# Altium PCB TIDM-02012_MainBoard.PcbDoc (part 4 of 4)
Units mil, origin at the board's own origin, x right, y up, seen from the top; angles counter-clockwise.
Board outline 6550 x 5100 mil, 4 copper layers (Top Layer, Layer 1, Layer 2, Bottom Layer), stack 81.2 mil thick; 300 components, 157 nets, 916 pads, 350 vias.
Unrouted connection lines stored in the file: 93.
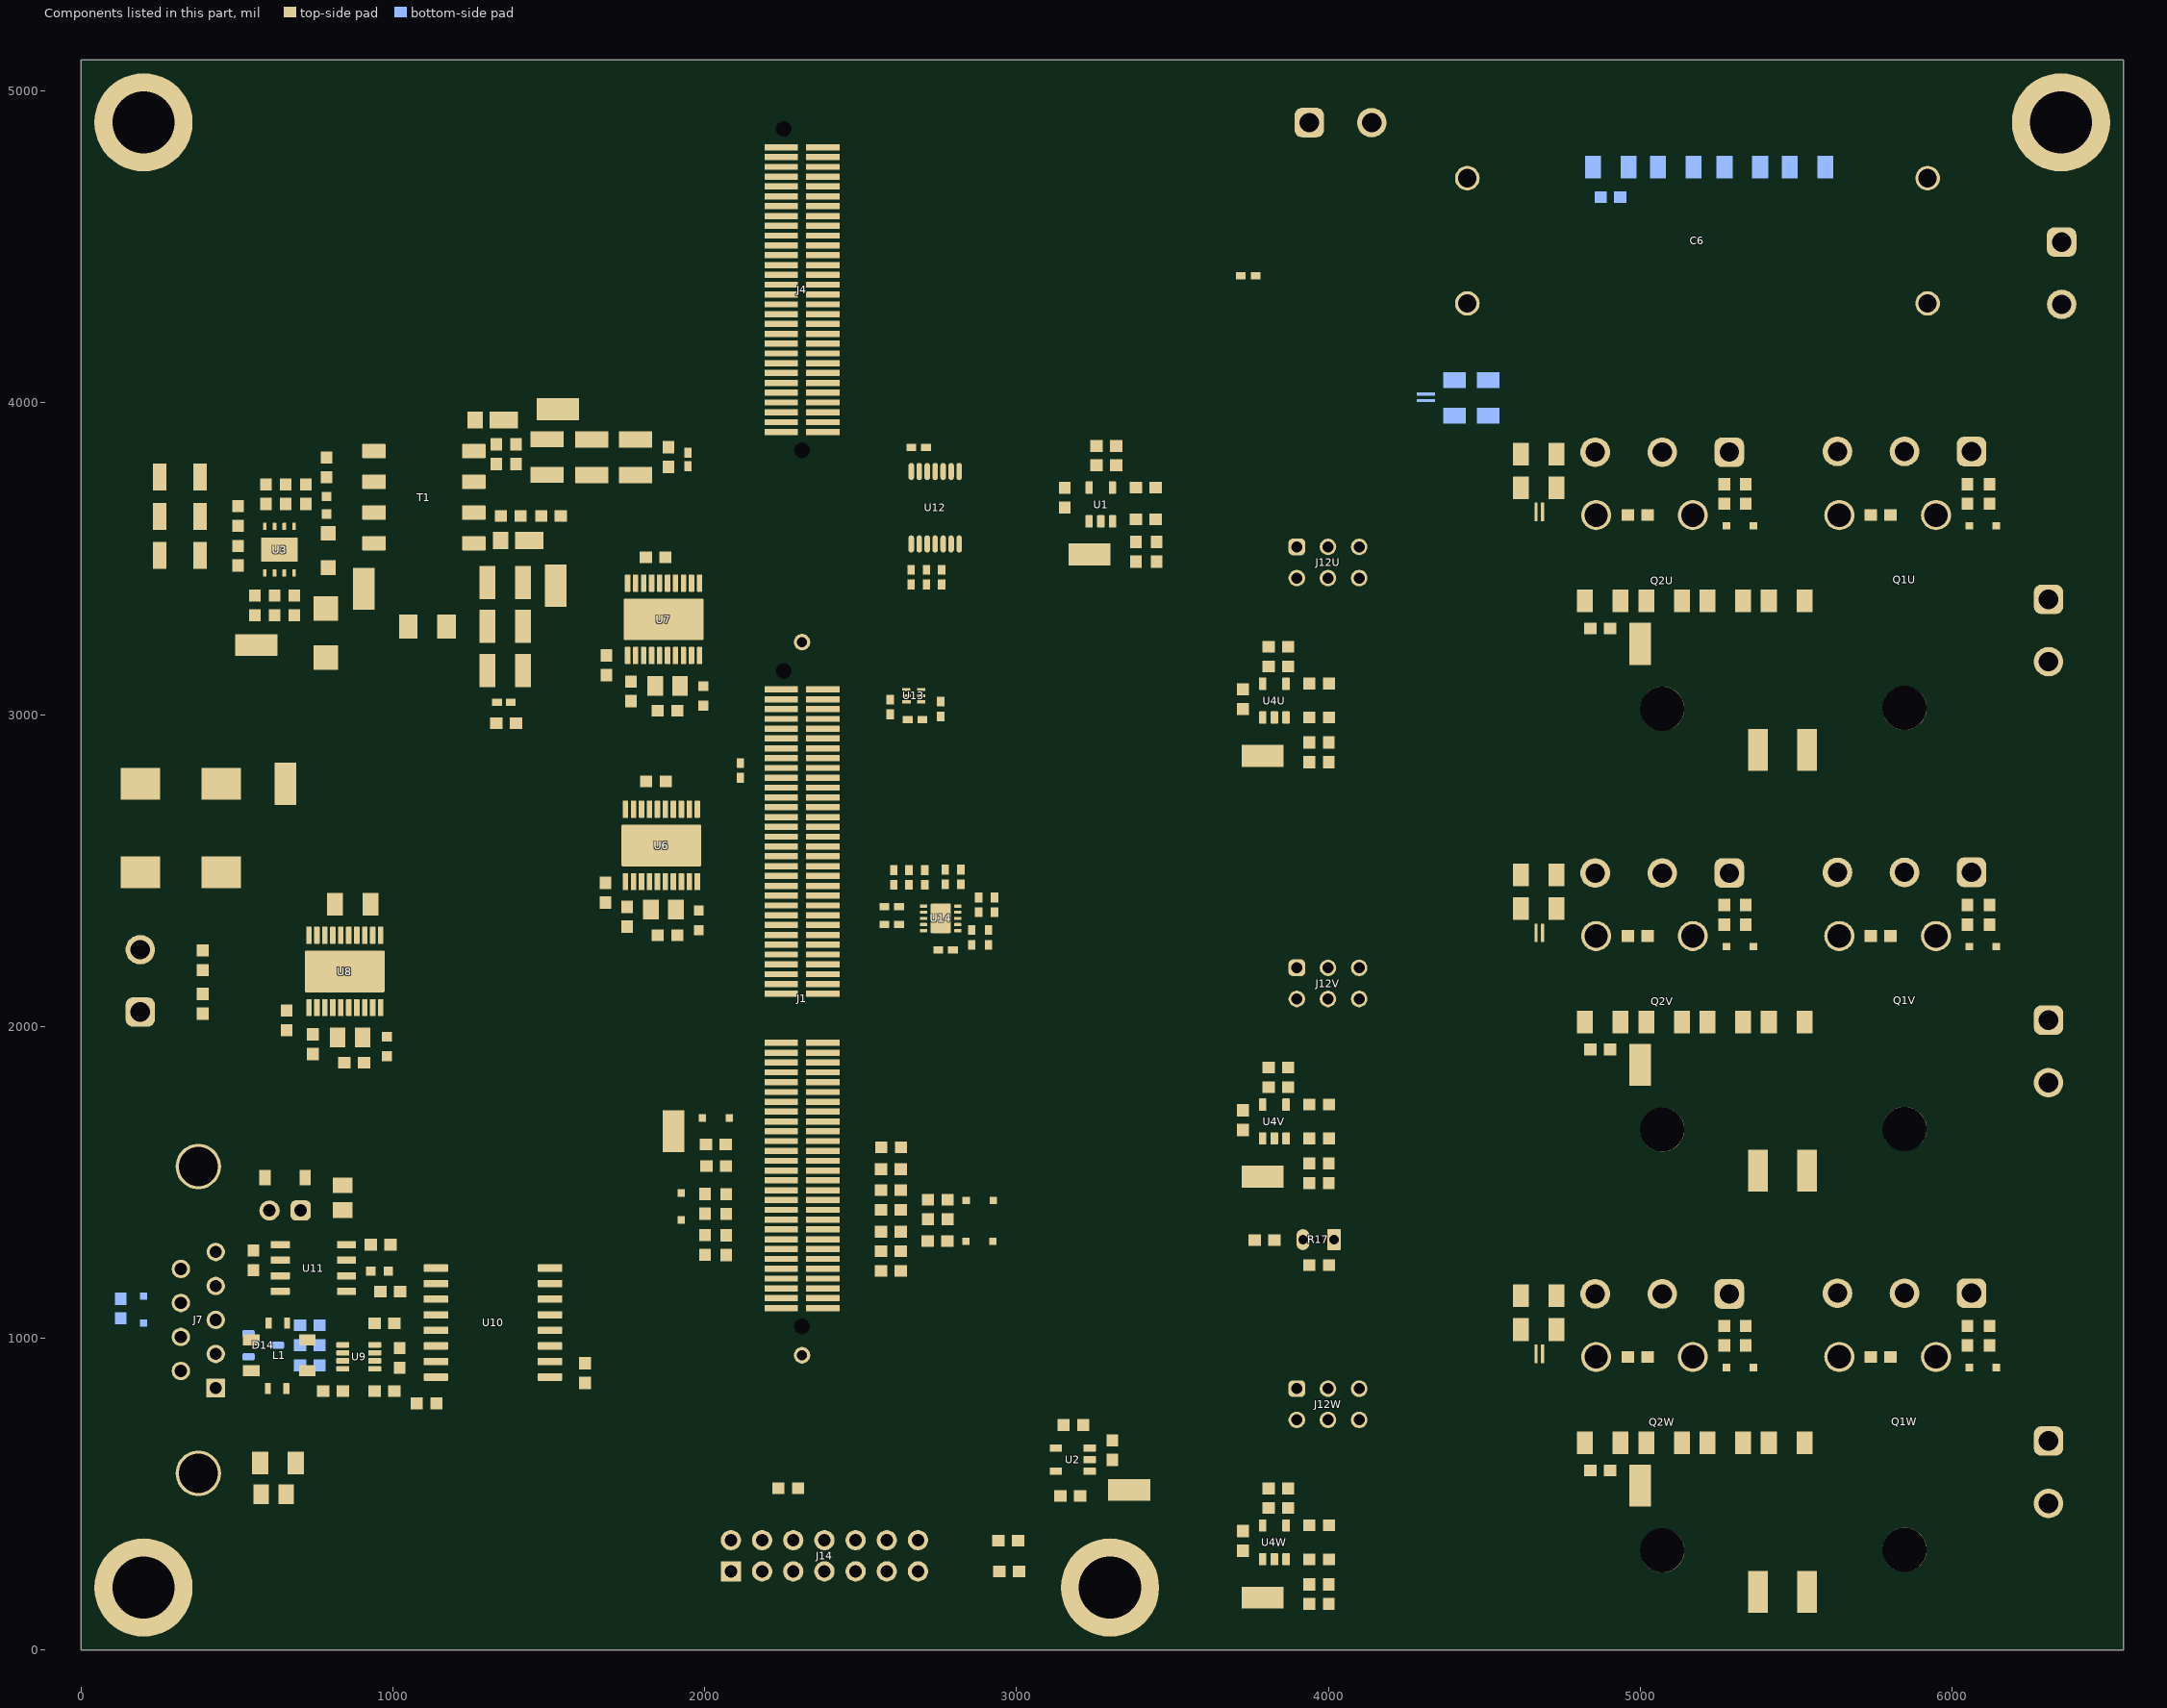
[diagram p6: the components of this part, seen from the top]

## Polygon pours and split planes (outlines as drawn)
GND_MCU on Bottom Layer "BOTTOM_LAYER_GND_MCU_P051" (solid, pour order 51): 1219.43,3944.93 1219.43,2692.41 1462,2449.84 1462,318 1716,64 4023.1,64 4135.65,176.54 4135.65,3784.05 3737.58,4182.11 3737.58,4833.67 3629.91,4941.34 1984.07,4941.34 1219.23,4176.5
S_1W on Bottom Layer "BOTTOM_LAYER_S_1W_P033" (solid, pour order 33): 6404.71,1225.32 6459,1171.02 6459,316 6356,213 5020.07,213 4903.64,329.43 4904.39,330.17 4904.39,1121.94 5007.76,1225.32
S_1V on Bottom Layer "BOTTOM_LAYER_S_1V_P032" (solid, pour order 32): 6404.71,2575.32 6459,2521.02 6459,1666 6356,1563 5020.07,1563 4903.64,1679.43 4904.39,1680.17 4904.39,2471.94 5007.76,2575.32
DC-U on Bottom Layer "BOTTOM_LAYER_DC-U_P042" (solid, pour order 42): 4369.49,3984 4357.23,3971.74 4357.23,3930.59 4244,3817.36 4244,952.54 4359.53,837.01 4746.54,837.01 4809.46,899.92 4809.46,3677.4 4554.64,3932.22 4554.64,3977.81 4548.45,3984
PGND on Bottom Layer "BOTTOM_LAYER_PGND_P039" (solid, pour order 39): 4236.75,4239.42 3928.13,4239.42 3778,4389.56 3778,4978 4745,4981 4828,4898 4828,4377.24 4559.28,4108.52 4559.28,4057.28 4550,4048 4368.02,4048 4357.36,4058.65 4357.27,4118.9
VBUS on Bottom Layer "BOTTOM_LAYER_VBUS_P037" (solid, pour order 37): 5610.66,4988 5869.81,4988 6202.39,4655.42 6202.39,4655.37 6499.16,4655.37 6499.16,4040 5612.19,4040
S_1U on Bottom Layer "BOTTOM_LAYER_S_1U_P031" (solid, pour order 31): 6404.71,3925.32 6459,3871.02 6459,3016 6356,2913 5020.07,2913 4903.64,3029.43 4904.39,3030.17 4904.39,3821.94 5007.76,3925.32
DC-U on Top Layer "Top Layer-DC-U" (solid, pour order 38): 4741.7,36 4244,533.7 4244,3888.02 4312.92,3956.94 4580.28,3956.94 4593.37,3943.85 4593.37,3913.2 4603.57,3903 4628,3903 4642.1,3888.9 4642.1,3674.1 4626,3658 4603.57,3658 4593.37,3647.8 4593.37,3210.3 4779.29,3024.39 5340.31,3024.39 5408.71,2955.98 5408.71,2786.08 5333.63,2711 4705.87,2711 4593.37,2598.5 4593.37,2563.2 4603.57,2553 4628,2553 4642.1,2538.9 4642.1,2324.1 4626,2308 4603.57,2308 4593.37,2297.8 4593.37,1860.3 4779.29,1674.39 5340.31,1674.39 5408.71,1605.98 5408.71,1436.08 5333.63,1361 4694.89,1361 4593.37,1259.48 4593.37,1213.2 4603.57,1203 4628,1203 4642.1,1188.9 4642.1,974.1 4626,958 4603.57,958 4593.37,947.8 4593.37,580.88 4849.87,324.39 5340.31,324.39 5408.71,255.98 5408.71,115.71 5329,36 4894,36
VCC33 on Top Layer "TOP_LAYER_VCC33_P048" (solid, pour order 48): 1801.97,2367.84 1773.56,2339.43 1773.56,2175.29 1793.23,2155.62 1865.41,2155.62 1881.16,2171.36 1880.84,2171.68 1880.84,2328.21 1841.21,2367.84
NetC32_2 on Top Layer "TOP_LAYER_NETC32_2_P045" (solid, pour order 45): 849.5,3492.43 836.93,3505 741.01,3505 666.55,3579.46 666.55,3673.8 692.1,3699.36 953,3699.36 977,3675.36 977,3524 977,3492.49 938.84,3454.33 875.02,3454.33 849.5,3479.85
VCC5_LV on Top Layer "TOP_LAYER_VCC5_LV_P044" (solid, pour order 44): 794.45,1935.72 776.46,1917.74 776.46,1859.68 793.14,1843 811,1843 863.92,1843 875.59,1854.67 875.59,1918.56 858.42,1935.72 858.42,1993.17 815.56,2036.04 807.93,2036.04 794.45,2035.97
PGND on Top Layer "TOP_LAYER_PGND_P040" (solid, pour order 40): 4236.75,4239.42 3928.13,4239.42 3778,4389.56 3778,4978 4745,4981 4828,4898 4828,4377.24 4559.28,4108.52 4559.28,4057.28 4550,4048 4368.02,4048 4357.36,4058.65 4357.27,4118.9
VBUS on Top Layer "TOP_LAYER_VBUS_P036" (solid, pour order 36): 5683.71,4988 5869.81,4988 6202.39,4655.42 6202.39,4655.37 6499.16,4655.37 6499.16,4040 5685.24,4040
VCC33 on Layer 2 "LAYER_2_VCC33_P055" (solid, pour order 55): 1219.43,3944.93 1219.43,2692.41 1462,2449.84 1462,318 1716,64 4023.1,64 4135.65,176.54 4135.65,3784.05 3737.58,4182.11 3737.58,4833.67 3629.91,4941.34 1984.07,4941.34 1219.23,4176.5
VCC5_LV on Layer 2 "LAYER_2_VCC5_LV_P047" (solid, pour order 47): 364.15,334.2 367.64,337.7 958.7,337.7 1183,562 1183,1998 1090.94,2090.06 610.06,2090.06 97,1577 97,601.35
VBUS on Layer 2 "LAYER_2_VBUS_P035" (solid, pour order 35): 5475,4988 5869.81,4988 6202.44,4655.37 6499.16,4655.37 6499.16,325.16 6252.27,78.27 5515.45,78.27 5420.5,173.22 5420.5,4933.5
GND_MCU on Layer 1 "LAYER_1_GND_MCU_P054" (solid, pour order 54): 1219.43,3944.93 1219.43,2692.41 1462,2449.84 1462,318 1716,64 4023.1,64 4135.65,176.54 4135.65,3784.05 3737.58,4182.11 3737.58,4833.67 3629.91,4941.34 1984.07,4941.34 1219.23,4176.5
GND on Layer 1 "LAYER_1_GND_P046" (solid, pour order 46): 373.57,324.77 97,601.35 97,4025 360,4288 749,4288 972,4065 972,2556 1183,2345 1183,562 949.16,328.16
DC-U on Layer 1 "LAYER_1_DC-U_P043" (solid, pour order 43): 4321.83,3936.34 4244,3858.51 4244,952.54 4359.53,837.01 4756.01,837.01 4931.47,1012.47 4931.47,3810.88 4806.01,3936.34
PGND on Layer 1 "LAYER_1_PGND_P041" (solid, pour order 41): 4236.75,4239.42 3928.13,4239.42 3778,4389.56 3778,4978 4745,4981 4828,4898 4828,4377.24 4559.28,4108.52 4559.28,4057.28 4550,4048 4368.02,4048 4357.36,4058.65 4357.27,4118.9
VBUS on Layer 1 "LAYER_1_VBUS_P034" (solid, pour order 34): 5475,4988 5869.81,4988 6202.44,4655.37 6499.16,4655.37 6499.16,325.16 6252.27,78.27 5515.45,78.27 5420.5,173.22 5420.5,4933.5

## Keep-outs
Keep-Out Layer:
  text ".Layer_Name" at 577,-858.49 h60

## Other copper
Top Layer:
  region net VBUS: 5504.36,277.07 5633,277.07 5633,97 5632,98 5504.79,98
  region net S_2W: 4701,1207 4701,994 4708,987 4809.46,987 4905,1082.54 4905,1179.47 4877.47,1207
  region net VBUS: 5504.36,1627.07 5633,1627.07 5633,1447 5632,1448 5504.79,1448
  region net S_2V: 4701,2557 4701,2344 4708,2337 4809.46,2337 4905,2432.54 4905,2529.47 4877.47,2557
  region net VBUS: 5504.36,2977.07 5633,2977.07 5633,2797 5632,2798 5504.79,2798
  region net S_2U: 4701,3907 4701,3694 4708,3687 4809.46,3687 4905,3782.54 4905,3879.47 4877.47,3907
  text ".Layer_Name" at 577,-858.49 h60
Bottom Layer:
  text ".Layer_Name" at 577,-858.49 h60

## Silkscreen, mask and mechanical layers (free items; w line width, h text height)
Top Overlay:
  lines w10: 935.68,62.68 1540.68,62.68 1540.68,551.86 935.68,551.86 935.68,62.68 ; 3849.03,688.37 4149.03,688.37 4149.03,887.58 3849.03,887.58 3849.03,688.37 ; 3849.03,2038.37 4149.03,2038.37 4149.03,2237.58 3849.03,2237.58 3849.03,2038.37 ; 3849.03,3388.37 4149.03,3388.37 4149.03,3587.58 3849.03,3587.58 3849.03,3388.37
  text "HVDC-" at 3905,4634 h60
  text "'.PRJ_Number'.PCB_Rev" at 596,4263 h108.27
  text "High Voltage Danger" at 2646,4144 h60
  text "HVDC+" at 6145.37,4060 h60
  text "800V" at 6137.71,3961.58 h100
  text "MAX" at 6342.71,3959.52 h60
  text "U" at 6378.84,3554.02 h60
  text "9 NM Torque" at 5460.26,3191.72 h60
  text "+" at 382.77,2313.99 h60
  text "V" at 6362.02,2208.41 h60
  text "-" at 382.77,1930.91 h60
  text "VBAT" at 162.08,1796.7 h60
  text "12V" at 190,1698.01 h100
  text "W" at 6362.02,845.46 h60
  text "CAN_H: 7 / CAN_L: 2 / LIN: 8 / GND: 3, 5" at 972,76.05 h60
  text "JTAG" at 2288,44.52 h60
  text ".Layer_Name" at 577,-858.49 h60
Bottom Overlay:
  text ".Layer_Name" at 577,-858.49 h60
Top Paste:
  text ".Layer_Name" at 577,-858.49 h60
Bottom Paste:
  text ".Layer_Name" at 577,-858.49 h60
Top Solder:
  text ".Layer_Name" at 577,-858.49 h60
  text ".Layer_Name" at 577,-858.49 h60
Bottom Solder:
  text ".Layer_Name" at 577,-858.49 h60
Drill Guide:
  text ".Layer_Name" at 577,-858.49 h60
M1 Board Outline:
  the board outline again, w10
  text ".Layer_Name" at 577,-858.49 h60
M2 Board Dimensions:
  rectangle: 0,-275 125,-150
  rectangle: 125,-400 500,-275
  lines w7: 0,-275 1000,-275 ; 125,-400 125,-150 ; 250,-400 250,-150 ; 500,-400 500,-150 ; 750,-400 750,-150 ; 0,-400 1000,-400 1000,-150 0,-150 0,-400
  text ".Layer_Name" at 577,-858.49 h60
M3 3D STEP Top:
  text ".Layer_Name" at 577,-858.49 h60
M4 3D STEP Bottom:
  text ".Layer_Name" at 577,-858.49 h60
M5 Assembly Top:
  lines w10: -292,-930.17 6308,-930.17 ; -292,-726.83 6310,-726.83 ; -292,-523.5 -292,-1133.5 3713,-1133.5 6310,-1133.5 6310,-523.5 -291.5,-523.5 -291.5,-1133.5 1284,-1133.5 ; 2173,-1133.5 2173,-523.5 ; 3440,-726.83 3440,-523.5 ; 4280,-726.83 4280,-523.5 ; 4902,-1140 4902,-937.17
  text "COMPONENTS MARKED 'DNP' SHOULD NOT BE POPULATED." at 1153.5,-318.5 h60
  text "ASSEMBLY VARIANT:" at 1153,-434 h60
  text ".VariantName" at 2189,-434 h60
  text "PCB VIEWED FROM TOP SIDE" at -228.5,-655.67 h60
  text "BOARD #:" at 2248,-655.67 h60
  text ".PRJ_Number" at 2793.5,-655.67 h60
  text "REV:" at 3638,-655.67 h60
  text ".PCB_Rev" at 3929.5,-655.67 h60
  text "SVN REV:" at 4476,-655.67 h60
  text ".VersionControl_RevNumber" at 4982,-655.67 h60
  text "TID #:" at 2248,-859 h60
  text ".TID" at 2793.5,-859 h60
  text "PLOT NAME =" at -228.5,-1064.34 h60
  text ".plot_File_Name" at 577,-1064.34 h60
  text "GENERATED    :" at 2250,-1064.34 h60
  text ".Print_Date" at 3119.5,-1064.34 h60
  text ".Print_Time" at 3848.5,-1064.34 h60
  text "TEXAS INSTRUMENTS" at 5113,-1064.34 h60
M6 Assembly Bottom:
  lines w10: -292.5,-727.33 6309.5,-727.33 ; -290.5,-930.67 6309.5,-930.67 ; 1115.5,-1140.5 1115.5,-937.67 ; 1737.5,-727.33 1737.5,-524 ; 2577.5,-727.33 2577.5,-524 ; 3844.5,-1134 3844.5,-524 ; 4733.5,-1134 6309,-1134 6309,-524 -292.5,-524 -292.5,-1134 2304.5,-1134 6309.5,-1134 6309.5,-524
  text "COMPONENTS MARKED 'DNP' SHOULD NOT BE POPULATED." at 6102,-318 h60
  text ".VariantName" at 5058,-434 h60
  text "ASSEMBLY VARIANT:" at 6097,-434 h60
  text ".VersionControl_RevNumber" at 1035.5,-656.17 h60
  text "SVN REV:" at 1541.5,-656.17 h60
  text ".PCB_Rev" at 2088,-656.17 h60
  text "REV:" at 2379.5,-656.17 h60
  text ".PRJ_Number" at 3224,-656.17 h60
  text "BOARD #:" at 3769.5,-656.17 h60
  text "PCB VIEWED FROM BOTTOM SIDE" at 6246,-656.17 h60
  text ".TID" at 3224,-859.5 h60
  text "TID #:" at 3769.5,-859.5 h60
  text "TEXAS INSTRUMENTS" at 904.5,-1064.84 h60
  text ".Print_Time" at 2169,-1064.84 h60
  text ".Print_Date" at 2898,-1064.84 h60
  text "GENERATED    :" at 3767.5,-1064.84 h60
  text ".plot_File_Name" at 5440.5,-1064.84 h60
  text "PLOT NAME =" at 6246,-1064.84 h60
M9 Title Sheet:
  drawing of 57 lines, arcs and shapes, not listed
  text "1" at 739.84,8036.5 h70
  text "2" at 3235.5,8036.5 h70
  text "3" at 5724.84,8036.5 h70
  text "4" at 8231.51,8036.5 h70
  text "5" at 10730.5,8036.5 h70
  text "6" at 13235.5,8036.5 h70
  text "A" at -416.5,6893.5 h70
  text "A" at 14383.5,6893.5 h70
  text "B" at -416.5,4513.5 h70
  text "B" at 14383.5,4513.5 h70
  text "C" at -416.5,2138.5 h70
  text "C" at 14383.5,2138.5 h70
  text "PROJECT TITLE:" at 11343.5,277.5 h45
  text ".PRJ_Title" at 11393.5,144.17 h70
  text "DESIGNED FOR:" at 11343.5,-23.5 h45
  text ".PRJ_Customer" at 11393.5,-163.5 h70
  text "D" at -416.5,-231.5 h70
  text "D" at 14383.5,-231.5 h70
  text "FILE NAME:" at 11343.5,-323.5 h45
  text ".PCB_File_Name_No_Path" at 11393.5,-443.5 h70
  text "Texas Instruments (TI) and/or its licensors do not warrant the accuracy or completeness of this specification" at 6374,-605.34 h45
  text "ENGINEER:" at 11343.5,-613.5 h45
  text "LAYOUT BY:" at 12848.5,-613.5 h45
  text "or any information contained therein. TI and/or its licensors do not warrant that this design will meet" at 6329.01,-718 h45
  text ".PRJ_Engineer" at 11393.5,-768.49 h70
  text ".PCB_Layout" at 12899,-768.49 h70
  text "the specifications, will be suitable for your application or fit for any particular purpose, or will operate in" at 6329.01,-830.67 h45
  text ".Layer_Name" at 577,-858.49 h60
  text "ALTIUM DESIGNER VERSION:" at 12848.5,-923.5 h45
  text "an implementation. TI and/or its licensors do not warrant that the design is production worthy. You should" at 6329.01,-943.33 h45
  text "completely validate and test your design implementation to confirm the system functionality for your application." at 6374,-1056 h45
  text ".print_Scale" at 11393.5,-1056.83 h70
  text ".Application_BuildNumber" at 12899,-1056.83 h70
  text "1" at 739.84,-1263.5 h70
  text "2" at 3235.5,-1263.5 h70
  text "3" at 5724.84,-1263.5 h70
  text "4" at 8231.51,-1263.5 h70
  text "5" at 10730.5,-1263.5 h70
  text "6" at 13235.5,-1263.5 h70
M10 Fab Notes:
  drawing of 189 lines, arcs and shapes, not listed
  text "DESIGN INFORMATION" at 12382.02,6356.17 h60
  text "MIN. TRACK WIDTH:" at 11737.46,6224.05 h60
  text "8" at 12833.7,6224.05 h60
  text "MIL" at 12988.46,6224.05 h60
  text "7.874" at 12667.32,6102.36 h60
  text "MIN. CLEARANCE:" at 11737.46,6099.92 h60
  text "MIL" at 12988.46,6099.92 h60
  text "MIN. VIA PAD SIZE:" at 11737.46,5975.8 h60
  text "24" at 12803.71,5975.8 h60
  text "MIL" at 12988.46,5975.8 h60
  text "0.05mm (2MIL)" at 12432.46,5845.9 h60
  text "MINIMUM ANNULAR RING" at 11408.23,5837.67 h60
  text "EXTERNAL" at 13140.46,5837.67 h60
  text "PER" at 11608.23,5727.55 h60
  text "IPC-D-275 CLASS 2 LEVEL C" at 11828.23,5727.54 h60
  text "MIL, HOLES" at 13316.46,5627.07 h60
  text "+/-" at 12924,5618.48 h60
  text "+/-" at 13778,5618.48 h60
  text "REGISTRATION TOLERANCES:" at 11408.23,5617.42 h60
  text "METAL" at 12608,5617.42 h60
  text "5" at 13184.2,5617.42 h60
  text "3" at 14017.2,5617.42 h60
  text "MIL" at 14133.46,5617.42 h60
  text "HOLE SIZE TOLERANCE (UNLESS OTHERWISE SPECIFIED):" at 11408.23,5519.1 h60
  text "+/-" at 13778,5516.23 h60
  text "3" at 14017.2,5515.17 h60
  text "MIL" at 14133.46,5515.17 h60
  text "MATERIAL:" at 11333.46,5377.52 h60
  text "FR-4 High Tg" at 12319.9,5249 h60
  text "X" at 12175.46,5241.01 h60
  text "FR-408" at 11754.46,5236.49 h60
  text "OTHER" at 13242.46,5236.49 h60
  text "62 MIL (1.6mm) +/-10%" at 12074.56,5093.46 h60
  text "X" at 11954.46,5091.01 h60
  text "THICKNESS:" at 11408.23,5085.24 h60
  text "OTHER" at 13359.46,5085.24 h60
  text "TOLERANCE:" at 11408.23,4946.92 h60
  text "X" at 12256.46,4946.92 h60
  text "ANSI IPC-6012 TYPE 3 CLASS 2" at 12434.48,4946.92 h60
  text "OTHER +/-" at 12434.46,4802.73 h60
  text "BOW & TWIST:" at 11408.23,4657.54 h60
  text "X" at 12256.46,4657.54 h60
  text "ANSI IPC-6012 TYPE 3 CLASS 2" at 12434.48,4657.54 h60
  text "OTHER +/-" at 12434.46,4510.85 h60
  text "DRILLING:" at 11333.46,4380.23 h60
  text "NC_DRILL FILES" at 13094.46,4275.04 h60
  text "REFERENCE:" at 11408.23,4271.1 h60
  text "X" at 12065.46,4271.01 h60
  text "AS SHOWN" at 12243.46,4271.1 h60
  text "X" at 12966.46,4271.1 h60
  text "OTHER" at 13392.46,4128.85 h60
  text "PTH COPPER THICKNESS:" at 11407.91,4125.32 h60
  text "X" at 12547.14,4125.32 h60
  text "20-30 um" at 12675.14,4125.32 h60
  text "BOARD FINISH:" at 11333.46,3977.73 h60
  text "SILKSCREEN:" at 11488.68,3867.6 h60
  text "X" at 12446.46,3867.6 h60
  text "TOP" at 12563.46,3867.6 h60
  text "X" at 12956.46,3867.6 h60
  text "BOTTOM" at 13074.46,3867.6 h60
  text "SILKSCREEN COLOR:" at 11488.68,3712.41 h60
  text "X" at 12445.46,3712.41 h60
  text "WHITE" at 12563.46,3712.41 h60
  text "OTHER" at 13074.46,3712.41 h60
  text "X" at 12576.46,3568.96 h60
  text "GREEN" at 12694.46,3568.96 h60
  text "OTHER" at 13312.46,3568.96 h60
  text "SOLDER RESIST COLOR:" at 11488.68,3562.1 h60
  text "X" at 12576.46,3414.71 h60
  text "MATTE" at 12694.46,3414.71 h60
  text "SEMI-GLOSS" at 13312,3414.07 h60
  text "IMMERSION GOLD (ENIG)" at 12394.46,3241.94 h60
  text "ENEPIG" at 13732,3234.72 h60
  text "SURFACE FINISH:" at 11333.46,3233.72 h60
  text "X" at 12216.46,3233.72 h60
  text "IMM. TIN/SILVER OR EQUIV" at 11663,3096.4 h60
  text "OTHER" at 13094.46,3092.47 h60
  text "ARRAY/PANEL:" at 11333.46,2937.09 h60
  text "CUT AND TRIM PER M1 BOARD OUTLINE" at 12394.46,2928.87 h60
  text "N.C. ROUTE" at 12394.46,2792.9 h60
  text "X" at 13082.46,2792.9 h60
  text "V. SCORE" at 13260.46,2792.9 h60
  text "CERTIFICATION:" at 11333.46,2663.77 h60
  text "MATERIALS AND WORKMANSHIP FOR ALL PCBS" at 12058.46,2663.77 h60
  text "TO MEET OR EXCEED THE REQUIREMENTS OF:" at 12058.46,2569.71 h60
  text "X" at 11695.97,2441.08 h60
  text "ANSI IPC-A-600F CLASS ->" at 11823.96,2441.08 h60
  text "X" at 13471.97,2441.08 h60
  text "2" at 13581.96,2441.08 h60
  text "1" at 13266.96,2439.58 h60
  text "3" at 13935.96,2439.58 h60
  text "X" at 12507.97,2293.39 h60
  text "RoHS" at 12635.96,2293.39 h60
  text "OTHER" at 13280.36,2293.39 h60
  text "PER ORDER" at 13677.42,2293.39 h60
  text "ALL BOARDS MUST MEET OR EXCEED UL94-V0 REQUIREMENTS." at 11361,2139.57 h60
  text "PCB MUST BEAR THE UL94V-0 UL REGISTERED MATERIAL ID NUMBER" at 11361,2023.5 h60
  text "ADDITIONAL REQUIREMENTS:" at 11333.46,1854.08 h60
  text "MICROSECTION:" at 11408.23,1746.95 h60
  text "YES" at 12313.96,1746.95 h60
  text "REQUIRED" at 13175.46,1602.62 h60
  text "BARE BOARD ELEC. TEST:" at 11408.23,1599.76 h60
  text "NONE" at 12713.96,1599.76 h60
  text "X" at 13057.46,1599.76 h60
  text "PER ORDER" at 13767.46,1599.76 h60
  text "XX MIL VIAS REQUIRE NON-CONDUCTIVE FILL AND PLANARIZE" at 11576.38,1394.82 h59
  text "XX MIL VIAS REQUIRE CONDUCTIVE FILL AND PLANARIZE" at 11584.38,1290.84 h60
  text "OUTER XX MIL TRACES REQUIRE 50 OHM SINGLE-ENDED IMPEDANCE" at 11583.39,1127.46 h58
  text "LAYER 2 & 3 (INNER LAYERS) XX MIL WIDE, XX MIL SPACE / TRACES REQUIRE 100 OHM DIFFERENTIAL IMPEDANCE" at 11575.39,891.74 h60
  text ".Layer_Name" at 577,-858.49 h60
M11 Gerber Information:
  lines w10: -292,-930.17 6308,-930.17 ; -292,-726.83 6310,-726.83 ; -292,-523.5 -292,-1133.5 3713,-1133.5 6310,-1133.5 6310,-523.5 -291.5,-523.5 -291.5,-1133.5 1284,-1133.5 ; 2173,-1133.5 2173,-523.5 ; 3440,-726.83 3440,-523.5 ; 4280,-726.83 4280,-523.5 ; 4902,-1140 4902,-937.17
  text "ALL ARTWORK VIEWED FROM TOP SIDE" at -228.5,-655.67 h60
  text "BOARD #:" at 2248,-655.67 h60
  text ".PRJ_Number" at 2793.5,-655.67 h60
  text "REV:" at 3638,-655.67 h60
  text ".PCB_Rev" at 3929.5,-655.67 h60
  text "SVN REV:" at 4476,-655.67 h60
  text ".VersionControl_RevNumber" at 4982,-655.67 h60
  text "LAYER NAME =" at -228.5,-858.49 h60
  text "TID #:" at 2248,-859 h60
  text ".TID" at 2793.5,-859 h60
  text "PLOT NAME =" at -228.5,-1064.34 h60
  text ".plot_File_Name" at 577,-1064.34 h60
  text "GENERATED    :" at 2250,-1064.34 h60
  text ".Print_Date" at 3119.5,-1064.34 h60
  text ".Print_Time" at 3848.5,-1064.34 h60
  text "TEXAS INSTRUMENTS" at 5113,-1064.34 h60
M12 Stackup:
  drawing of 295 lines, arcs and shapes, not listed
  text "Layer" at 9821.59,7874.94 h60
  text "Name" at 10231.51,7874.94 h60
  text "Material" at 11161.25,7874.94 h60
  text "Thickness" at 12021.02,7874.94 h60
  text "Constant" at 12670.85,7874.94 h60
  text "Board Layer Stack" at 13240.71,7874.94 h60
  text "Top Overlay" at 10231.51,7754.94 h60
  text "Top Solder" at 10231.51,7634.94 h60
  text "Solder Resist" at 11161.25,7634.94 h60
  text "0.40mil" at 12021.02,7634.94 h60
  text "3.5" at 12670.85,7634.94 h60
  text "1" at 9821.59,7514.94 h60
  text "Top Layer" at 10231.51,7514.94 h60
  text "2.80mil" at 12021.02,7514.94 h60
  text "Dielectric 1" at 10231.51,7394.94 h60
  text "Core-009" at 11161.25,7394.94 h60
  text "15.00mil" at 12021.02,7394.94 h60
  text "4.5" at 12670.85,7394.94 h60
  text "2" at 9821.59,7274.94 h60
  text "Layer 1" at 10231.51,7274.94 h60
  text "CF-004" at 11161.25,7274.94 h60
  text "2.80mil" at 12021.02,7274.94 h60
  text "Dielectric1" at 10231.51,7154.94 h60
  text "FR-4 High Tg" at 11161.25,7154.94 h60
  text "40.00mil" at 12021.02,7154.94 h60
  text "4.8" at 12670.85,7154.94 h60
  text "3" at 9821.59,7034.94 h60
  text "Layer 2" at 10231.51,7034.94 h60
  text "CF-004" at 11161.25,7034.94 h60
  text "2.80mil" at 12021.02,7034.94 h60
  text "Dielectric 2" at 10231.51,6914.94 h60
  text "Core-009" at 11161.25,6914.94 h60
  text "15.00mil" at 12021.02,6914.94 h60
  text "4.5" at 12670.85,6914.94 h60
  text "4" at 9821.59,6794.94 h60
  text "Bottom Layer" at 10231.51,6794.94 h60
  text "2.80mil" at 12021.02,6794.94 h60
  text "Bottom Solder" at 10231.51,6674.94 h60
  text "Solder Resist" at 11161.25,6674.94 h60
  text "0.40mil" at 12021.02,6674.94 h60
  text "3.5" at 12670.85,6674.94 h60
  text "Bottom Overlay" at 10231.51,6554.94 h60
  text ".Layer_Name" at 577,-858.49 h60
M13 Component Bodies Top:
  text ".Layer_Name" at 577,-858.49 h60
M14 Component Bodies Bottom:
  text ".Layer_Name" at 577,-858.49 h60
M15 Courtyards Top:
  text ".Layer_Name" at 577,-858.49 h60
M16 Courtyards Bottom:
  text ".Layer_Name" at 577,-858.49 h60
Drill Drawing:
  drawing of 160 lines, arcs and shapes, not listed
  text "Symbol" at 7501.76,5489.1 h72
  text "Quantity" at 7801.91,5489.1 h72
  text "Finished Hole Size" at 8133.6,5489.1 h72
  text "Plated" at 8769.46,5489.1 h72
  text "Hole Type" at 9028.26,5489.1 h72
  text "Drill Layer Pair" at 9403.01,5489.1 h72
  text "Hole Tolerance" at 10125.55,5489.1 h72
  text "1" at 7801.91,5365.07 h60
  text "29.53mil (0.750mm)" at 8133.6,5365.07 h60
  text "NPTH" at 8769.46,5365.07 h60
  text "Round" at 9028.26,5365.07 h60
  text "Top Layer - Bottom Layer" at 9403.01,5365.07 h60
  text "B" at 7476.51,5355.08 h55.12
  text "4" at 7801.91,5241.05 h60
  text "50.00mil (1.270mm)" at 8133.6,5241.05 h60
  text "NPTH" at 8769.46,5241.05 h60
  text "Round" at 9028.26,5241.05 h60
  text "Top Layer - Bottom Layer" at 9403.01,5241.05 h60
  text "6" at 7801.91,5117.02 h60
  text "141.73mil (3.600mm)" at 8133.6,5117.02 h60
  text "NPTH" at 8769.46,5117.02 h60
  text "Round" at 9028.26,5117.02 h60
  text "Top Layer - Bottom Layer" at 9403.01,5117.02 h60
  text "254" at 7801.91,4992.99 h60
  text "10.00mil (0.254mm)" at 8133.6,4992.99 h60
  text "PTH" at 8769.46,4992.99 h60
  text "Round" at 9028.26,4992.99 h60
  text "Top Layer - Bottom Layer" at 9403.01,4992.99 h60
  text "C" at 7476.51,4983 h55.12
  text "22" at 7801.91,4868.97 h60
  text "16.00mil (0.406mm)" at 8133.6,4868.97 h60
  text "PTH" at 8769.46,4868.97 h60
  text "Round" at 9028.26,4868.97 h60
  text "Top Layer - Bottom Layer" at 9403.01,4868.97 h60
  text "5" at 7801.91,4744.94 h60
  text "25.00mil (0.635mm)" at 8133.6,4744.94 h60
  text "PTH" at 8769.46,4744.94 h60
  text "Round" at 9028.26,4744.94 h60
  text "Top Layer - Bottom Layer" at 9403.01,4744.94 h60
  text "D" at 7476.51,4734.95 h55.12
  text "69" at 7801.91,4620.91 h60
  text "28.00mil (0.711mm)" at 8133.6,4620.91 h60
  text "PTH" at 8769.46,4620.91 h60
  text "Round" at 9028.26,4620.91 h60
  text "Top Layer - Bottom Layer" at 9403.01,4620.91 h60
  text "2" at 7801.91,4496.89 h60
  text "29.53mil (0.750mm)" at 8133.6,4496.89 h60
  text "PTH" at 8769.46,4496.89 h60
  text "Round" at 9028.26,4496.89 h60
  text "Top Layer - Bottom Layer" at 9403.01,4496.89 h60
  text "A" at 7476.51,4486.89 h55.12
  text "2" at 7801.91,4372.86 h60
  text "33.07mil (0.840mm)" at 8133.6,4372.86 h60
  text "PTH" at 8769.46,4372.86 h60
  text "Round" at 9028.26,4372.86 h60
  text "Top Layer - Bottom Layer" at 9403.01,4372.86 h60
  text "18" at 7801.91,4248.83 h60
  text "35.43mil (0.900mm)" at 8133.6,4248.83 h60
  text "PTH" at 8769.46,4248.83 h60
  text "Round" at 9028.26,4248.83 h60
  text "Top Layer - Bottom Layer" at 9403.01,4248.83 h60
  text "+/-3.15mil" at 10125.55,4248.83 h60
  text "9" at 7801.91,4124.8 h60
  text "39.37mil (1.000mm)" at 8133.6,4124.8 h60
  text "PTH" at 8769.46,4124.8 h60
  text "Round" at 9028.26,4124.8 h60
  text "Top Layer - Bottom Layer" at 9403.01,4124.8 h60
  text "16" at 7801.91,4000.78 h60
  text "40.00mil (1.016mm)" at 8133.6,4000.78 h60
  text "PTH" at 8769.46,4000.78 h60
  text "Round" at 9028.26,4000.78 h60
  text "Top Layer - Bottom Layer" at 9403.01,4000.78 h60
  text "4" at 7801.91,3876.75 h60
  text "59.06mil (1.500mm)" at 8133.6,3876.75 h60
  text "PTH" at 8769.46,3876.75 h60
  text "Round" at 9028.26,3876.75 h60
  text "Top Layer - Bottom Layer" at 9403.01,3876.75 h60
  text "18" at 7801.91,3752.72 h60
  text "62.00mil (1.575mm)" at 8133.6,3752.72 h60
  text "PTH" at 8769.46,3752.72 h60
  text "Round" at 9028.26,3752.72 h60
  text "Top Layer - Bottom Layer" at 9403.01,3752.72 h60
  text "12" at 7801.91,3628.7 h60
  text "62.99mil (1.600mm)" at 8133.6,3628.7 h60
  text "PTH" at 8769.46,3628.7 h60
  text "Round" at 9028.26,3628.7 h60
  text "Top Layer - Bottom Layer" at 9403.01,3628.7 h60
  text "+/-5.91mil" at 10125.55,3628.7 h60
  text "12" at 7801.91,3504.67 h60
  text "75.00mil (1.905mm)" at 8133.6,3504.67 h60
  text "PTH" at 8769.46,3504.67 h60
  text "Round" at 9028.26,3504.67 h60
  text "Top Layer - Bottom Layer" at 9403.01,3504.67 h60
  text "2" at 7801.91,3380.64 h60
  text "125.98mil (3.200mm)" at 8133.6,3380.64 h60
  text "PTH" at 8769.46,3380.64 h60
  text "Round" at 9028.26,3380.64 h60
  text "Top Layer - Bottom Layer" at 9403.01,3380.64 h60
  text "4" at 7801.91,3256.62 h60
  text "200.00mil (5.080mm)" at 8133.6,3256.62 h60
  text "PTH" at 8769.46,3256.62 h60
  text "Round" at 9028.26,3256.62 h60
  text "Top Layer - Bottom Layer" at 9403.01,3256.62 h60
  text "460 Total" at 7801.91,3132.59 h60
  text ".Layer_Name" at 577,-858.49 h60
M17 Embedded Cavity:
  text ".Layer_Name" at 577,-858.49 h60
M18 Embedded Assembly:
  text ".Layer_Name" at 577,-858.49 h60
M19 Embedded Keepout:
  text ".Layer_Name" at 577,-858.49 h60

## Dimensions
5639,3640 to 5949,3640 on M5 Assembly Top
5169,3640 to 5639,3640 on M5 Assembly Top
4859,3640 to 5169,3640 on M5 Assembly Top
4099,3438 to 4859,3640 on M5 Assembly Top
4859,3640 to 4099,3538 on M5 Assembly Top
0,5100 to 0,0 on M2 Board Dimensions
0,0 to 6550,0 on M2 Board Dimensions
0,-400 to 1000,-400 on M2 Board Dimensions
